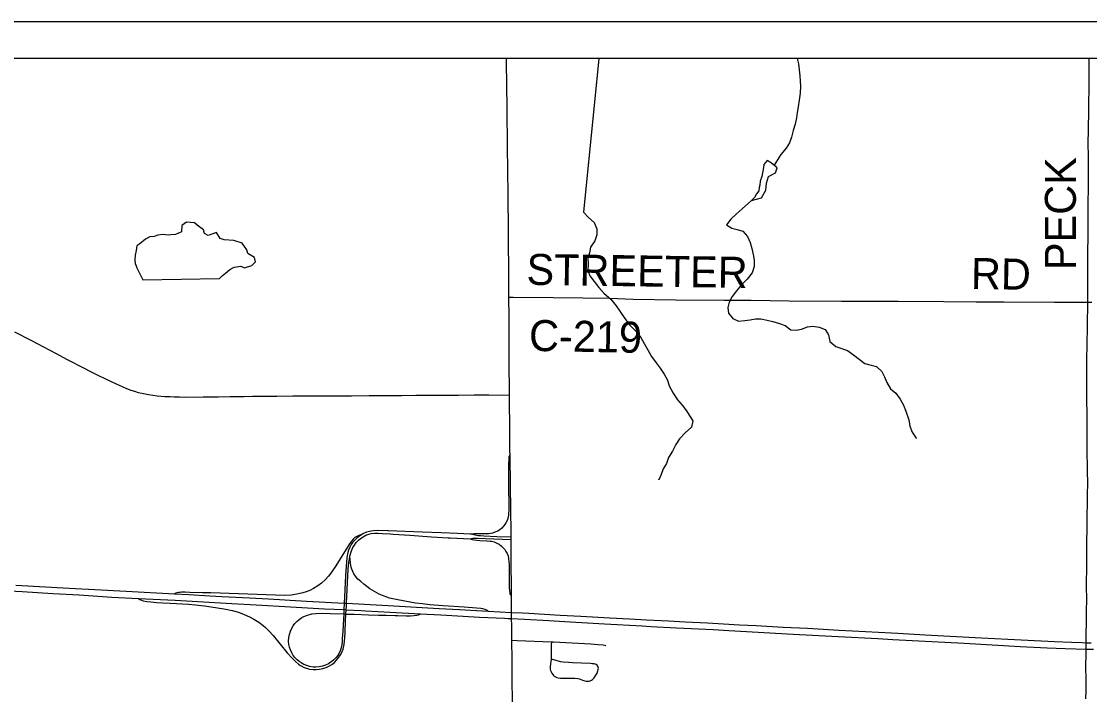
# Model space of a CAD drawing. Extents: x 0 to 34, y 0 to 22.
# Drawn here: x 24.966 to 26.924, y 15.541 to 16.775 of the extents above; entities that cross this region are included whole.
import ezdxf

# ---------------------------------------------------------------- set-up
doc = ezdxf.new("R2010")
doc.units = 0
for name, color, linetype in [('GM_X_Corporation', 7, 'Continuous'), ('GM_X_County_Road', 7, 'Continuous'), ('GM_X_County_Road_Text', 7, 'Continuous'), ('GM_X_Interchange_Ramps', 7, 'Continuous'), ('GM_X_Interstate_Route', 7, 'Continuous'), ('GM_X_Minor_Lake', 7, 'Continuous'), ('GM_X_Minor_River', 7, 'Continuous'), ('GM_X_State_Route', 7, 'Continuous'), ('GM_X_Township_Road', 7, 'Continuous'), ('SH_Data', 7, 'Continuous')]:
    doc.layers.add(name, color=color, linetype=linetype)

msp = doc.modelspace()

# ---------------------------------------------------------------- linework, layer by layer
at = {"layer": 'GM_X_Corporation'}
msp.add_lwpolyline([(27.8821, 16.7067), (23.0715, 16.7067), (23.0715, 12.7151)], dxfattribs=at)
at = {"layer": 'GM_X_County_Road'}
for points in [[(26.9208, 16.2606), (26.9208, 16.267), (26.9209, 16.3006), (26.9213, 16.3441), (26.9219, 16.3889), (26.9215, 16.4106), (26.9218, 16.4423), (26.9221, 16.469), (26.9223, 16.4951), (26.9225, 16.5131), (26.9221, 16.5316), (26.9219, 16.5477), (26.9222, 16.58), (26.9227, 16.6086), (26.9229, 16.6259), (26.9232, 16.6358), (26.9233, 16.6408), (26.9236, 16.6578), (26.9235, 16.6929), (26.9235, 16.7027), (26.9236, 16.7067)], [(25.86, 16.2697), (25.8681, 16.2697), (25.9413, 16.2689), (25.9953, 16.2685), (26.0445, 16.2678), (26.0877, 16.2661), (26.1655, 16.2648), (26.2546, 16.264), (26.3042, 16.264), (26.3734, 16.2631), (26.4694, 16.2624), (26.5166, 16.2622), (26.5732, 16.2622), (26.6571, 16.2616), (26.7167, 16.2613), (26.7676, 16.2608), (26.8602, 16.2604), (26.9208, 16.2606)], [(26.9177, 15.5337), (26.9178, 15.5492), (26.9179, 15.5673), (26.9178, 15.5753), (26.9177, 15.5865), (26.9177, 15.5908), (26.9179, 15.6182), (26.918, 15.6249), (26.918, 15.6319), (26.918, 15.6366), (26.9182, 15.6536), (26.9185, 15.6723), (26.9185, 15.6884), (26.9187, 15.6959), (26.919, 15.7145), (26.9189, 15.7412), (26.9193, 15.7778), (26.9192, 15.7915), (26.9192, 15.7988), (26.9192, 15.8007), (26.9192, 15.8048), (26.919, 15.8135), (26.9192, 15.8278), (26.9196, 15.8383), (26.9198, 15.8476), (26.92, 15.855), (26.92, 15.8579), (26.9201, 15.8721), (26.9203, 15.8889), (26.9207, 15.9088), (26.9208, 15.928), (26.9204, 15.9522), (26.92, 15.9925), (26.9201, 16.0145), (26.92, 16.0413), (26.9193, 16.0955), (26.9191, 16.1361), (26.9194, 16.1551), (26.9198, 16.1825), (26.9203, 16.2167), (26.9208, 16.2606)], [(26.9208, 16.2606), (26.9287, 16.2605)]]:
    msp.add_lwpolyline(points, dxfattribs=at)
at = {"layer": 'GM_X_Interchange_Ramps'}
msp.add_line((25.7526, 15.8286), (25.7889, 15.827), dxfattribs=at)
for points in [[(25.8621, 15.9806), (25.8615, 15.9803), (25.8609, 15.9798), (25.8603, 15.9784), (25.8601, 15.9772), (25.8597, 15.9722), (25.8593, 15.9644), (25.859, 15.9396), (25.8593, 15.9207), (25.8596, 15.8892), (25.8596, 15.8794), (25.8595, 15.8732), (25.8593, 15.8704), (25.8587, 15.8669), (25.858, 15.8642), (25.8567, 15.8604), (25.8545, 15.8559), (25.8527, 15.8529), (25.8504, 15.8498), (25.8473, 15.8466), (25.844, 15.844), (25.8397, 15.8412), (25.8345, 15.8388), (25.8297, 15.8372), (25.8261, 15.8366), (25.8226, 15.8363), (25.8162, 15.8363), (25.8104, 15.8363), (25.8023, 15.836), (25.7962, 15.836), (25.7892, 15.8357)], [(25.6382, 15.8416), (25.6187, 15.842), (25.612, 15.8416), (25.6047, 15.8404), (25.5988, 15.8389), (25.5933, 15.8365), (25.5918, 15.8356)], [(25.7892, 15.8357), (25.7658, 15.8365), (25.736, 15.8376), (25.701, 15.8389), (25.6392, 15.8416), (25.6382, 15.8416)], [(25.5918, 15.8356), (25.5886, 15.8344), (25.5847, 15.833), (25.581, 15.8313), (25.5778, 15.829), (25.5747, 15.8262), (25.572, 15.8231), (25.5681, 15.8175), (25.5508, 15.7902), (25.5428, 15.7776), (25.5334, 15.7637), (25.5293, 15.7583), (25.5235, 15.7518), (25.5166, 15.7456), (25.5096, 15.7405), (25.5021, 15.736), (25.4949, 15.7324), (25.4868, 15.7293), (25.4797, 15.7271), (25.4712, 15.7252), (25.4607, 15.7238), (25.4489, 15.7233), (25.4321, 15.7234), (25.314, 15.7277), (25.2982, 15.7281), (25.2753, 15.7287), (25.2666, 15.7289), (25.2602, 15.7289), (25.2568, 15.7288), (25.2546, 15.7284), (25.2516, 15.7278), (25.2495, 15.7271), (25.247, 15.7262)], [(25.5918, 15.8356), (25.587, 15.8325), (25.5819, 15.8286), (25.5776, 15.8246), (25.5742, 15.8205), (25.5712, 15.8164), (25.5685, 15.8113), (25.5661, 15.806), (25.5642, 15.7996), (25.563, 15.7923), (25.5622, 15.7839), (25.5618, 15.7768), (25.5608, 15.7592), (25.5588, 15.7209), (25.5582, 15.7089), (25.5577, 15.6971), (25.5573, 15.6892), (25.5568, 15.6793), (25.5556, 15.6574), (25.5547, 15.644), (25.5543, 15.6383), (25.5538, 15.6329), (25.5531, 15.6294), (25.552, 15.6255), (25.5507, 15.6214), (25.5487, 15.6173), (25.5457, 15.6128), (25.5429, 15.609), (25.5383, 15.6043), (25.5339, 15.6009), (25.5292, 15.5979), (25.5241, 15.5954), (25.5185, 15.5936), (25.5125, 15.5922), (25.5063, 15.5917), (25.5011, 15.592), (25.4947, 15.593), (25.4894, 15.5945), (25.4841, 15.5967), (25.4794, 15.5994), (25.4755, 15.6019), (25.4717, 15.6051), (25.4678, 15.6092), (25.4646, 15.6132), (25.4619, 15.6177), (25.4595, 15.6232), (25.458, 15.6283), (25.4568, 15.6331), (25.4563, 15.6393), (25.4569, 15.646), (25.4578, 15.6515), (25.4595, 15.6575), (25.4615, 15.662), (25.4645, 15.6674), (25.4679, 15.672), (25.4712, 15.6756), (25.4755, 15.6793), (25.4806, 15.6827), (25.4839, 15.6844), (25.4908, 15.6872), (25.4987, 15.6892), (25.5067, 15.6902), (25.516, 15.6905), (25.5327, 15.69), (25.5568, 15.6892)], [(25.5686, 15.7953), (25.5716, 15.8051), (25.574, 15.8107), (25.5768, 15.8155), (25.58, 15.8199), (25.5841, 15.8244), (25.5879, 15.8275), (25.593, 15.8308), (25.5979, 15.8333), (25.6035, 15.8353), (25.6077, 15.8364), (25.6137, 15.8373), (25.6204, 15.8374), (25.6285, 15.8367), (25.6423, 15.8358)], [(25.6423, 15.8358), (25.6482, 15.8354), (25.6784, 15.8335), (25.718, 15.8307), (25.7486, 15.8288), (25.7526, 15.8286)], [(25.7889, 15.827), (25.7912, 15.8277), (25.7939, 15.828), (25.7979, 15.8281), (25.8027, 15.828), (25.8326, 15.8268), (25.864, 15.8255)], [(25.7889, 15.827), (25.7926, 15.8258), (25.7965, 15.8249), (25.801, 15.8244), (25.8066, 15.8241), (25.8197, 15.8232), (25.8254, 15.8228), (25.8281, 15.8225), (25.8306, 15.822), (25.8328, 15.8214), (25.8353, 15.8204), (25.8381, 15.8192), (25.8424, 15.8168), (25.8463, 15.8137), (25.8491, 15.8109), (25.8523, 15.8071), (25.8546, 15.8038), (25.8568, 15.7998), (25.8584, 15.7956), (25.8595, 15.7902), (25.8601, 15.7852), (25.8603, 15.7793), (25.8604, 15.7591), (25.8604, 15.7516), (25.8607, 15.7369), (25.8615, 15.7279), (25.8619, 15.7261), (25.8628, 15.7243), (25.8636, 15.7235), (25.8647, 15.7228)], [(25.864, 15.8299), (25.8382, 15.8306), (25.814, 15.8318), (25.8079, 15.8322), (25.8038, 15.8326), (25.798, 15.8335), (25.793, 15.8345), (25.7892, 15.8357)], [(25.1814, 15.7176), (25.1835, 15.7159), (25.1865, 15.7144), (25.1898, 15.7134), (25.1965, 15.7123), (25.2036, 15.7113), (25.2147, 15.7105), (25.2259, 15.7098), (25.2389, 15.7092), (25.2507, 15.7085), (25.2619, 15.7079), (25.273, 15.7069), (25.2854, 15.706), (25.3021, 15.7042), (25.3224, 15.7013), (25.3414, 15.698), (25.353, 15.6955), (25.3643, 15.6924), (25.3748, 15.6885), (25.3845, 15.6841), (25.3926, 15.6796), (25.4016, 15.674), (25.4095, 15.668), (25.4137, 15.6643), (25.4204, 15.6579), (25.428, 15.6496), (25.4539, 15.6178), (25.4626, 15.608), (25.4688, 15.6019), (25.4746, 15.5972), (25.4782, 15.5947), (25.4848, 15.5913), (25.4906, 15.5892), (25.4948, 15.5882), (25.501, 15.5874), (25.5066, 15.5874), (25.5128, 15.588), (25.5189, 15.5893), (25.5248, 15.5913), (25.5299, 15.5936), (25.5352, 15.5968), (25.5401, 15.6006), (25.5446, 15.6049), (25.5485, 15.6098), (25.5518, 15.615), (25.5545, 15.6206), (25.556, 15.6247), (25.5579, 15.6332), (25.5592, 15.6455), (25.5598, 15.6561), (25.5608, 15.6772), (25.5614, 15.6891), (25.5618, 15.6968), (25.5621, 15.7033), (25.5624, 15.7087), (25.5636, 15.7338), (25.5657, 15.771), (25.5669, 15.784), (25.5676, 15.7895), (25.5686, 15.7953)], [(25.8223, 15.6945), (25.8202, 15.6955), (25.8168, 15.6972), (25.8124, 15.6985), (25.8084, 15.6992), (25.8008, 15.6999), (25.7779, 15.7015), (25.7395, 15.7039), (25.7154, 15.7059), (25.7018, 15.7075), (25.6889, 15.7093), (25.6693, 15.7125), (25.6534, 15.7155), (25.6413, 15.7184), (25.6313, 15.7217), (25.6222, 15.7256), (25.6134, 15.7302), (25.605, 15.7355), (25.594, 15.7437), (25.5884, 15.7486), (25.5834, 15.7532), (25.5789, 15.7584), (25.5759, 15.763), (25.5737, 15.7669), (25.572, 15.7715), (25.571, 15.7752), (25.5698, 15.782), (25.5686, 15.7953)], [(25.5579, 15.6892), (25.5614, 15.6891), (25.5678, 15.6889), (25.5764, 15.6886), (25.6025, 15.6876), (25.6213, 15.6871), (25.6348, 15.6868), (25.6514, 15.6862), (25.6558, 15.6861), (25.6716, 15.6857), (25.6796, 15.6857), (25.6856, 15.6861), (25.6911, 15.6868), (25.6942, 15.6879), (25.6982, 15.6896)]]:
    msp.add_lwpolyline(points, dxfattribs=at)
at = {"layer": 'GM_X_Interstate_Route'}
for points in [[(24.9207, 15.7329), (24.9681, 15.7301), (25.0241, 15.7269), (25.0725, 15.7241), (25.1322, 15.7202), (25.1814, 15.7176), (25.2483, 15.7143), (25.3104, 15.7108), (25.3523, 15.7084), (25.3966, 15.7059), (25.4596, 15.7025), (25.5222, 15.6989), (25.5577, 15.6971), (25.5618, 15.6968), (25.5895, 15.6954)], [(24.9563, 15.7419), (25.0543, 15.7365), (25.1008, 15.7339), (25.1586, 15.7308), (25.247, 15.7262)], [(25.247, 15.7262), (25.2731, 15.7247), (25.3119, 15.7225), (25.3339, 15.7213), (25.3845, 15.7185), (25.4194, 15.7167), (25.4888, 15.7128), (25.5465, 15.7095), (25.5582, 15.7089), (25.5624, 15.7087), (25.639, 15.7046), (25.7325, 15.6995), (25.7697, 15.6974), (25.8223, 15.6945), (25.8649, 15.6921), (25.8847, 15.691), (25.8963, 15.6904), (25.9542, 15.6873), (25.9916, 15.6854), (26.045, 15.6824), (26.081, 15.6804), (26.1123, 15.6787), (26.1525, 15.6765), (26.1828, 15.6748), (26.2238, 15.6728), (26.2824, 15.6696), (26.3132, 15.6678), (26.3624, 15.6653), (26.4074, 15.6629), (26.4369, 15.6613), (26.4649, 15.6597), (26.4895, 15.6582), (26.5374, 15.6557), (26.5726, 15.6539), (26.6231, 15.651), (26.7261, 15.6454), (26.7988, 15.6416), (26.8601, 15.6386), (26.8909, 15.6373), (26.9106, 15.6368), (26.918, 15.6366), (26.927, 15.6365)], [(25.5895, 15.6954), (25.5974, 15.695), (25.6422, 15.6926), (25.6982, 15.6896), (25.735, 15.6875), (25.776, 15.6852), (25.8061, 15.6836), (25.8517, 15.6813), (25.8578, 15.681)], [(25.8578, 15.681), (25.865, 15.6807), (25.8885, 15.6796), (25.9333, 15.6771), (25.9723, 15.6749), (26.0039, 15.6732), (26.0354, 15.6714), (26.1041, 15.6675), (26.1204, 15.6665), (26.1669, 15.6641), (26.2344, 15.6605), (26.263, 15.6589), (26.381, 15.6523), (26.4637, 15.648), (26.5363, 15.644), (26.564, 15.6425), (26.6943, 15.6355), (26.797, 15.6299), (26.8468, 15.6272), (26.8797, 15.6258), (26.918, 15.6249), (26.9314, 15.6246)]]:
    msp.add_lwpolyline(points, dxfattribs=at)
at = {"layer": 'GM_X_Minor_Lake'}
for p, q in [((26.3264, 16.5073), (26.3234, 16.4906)), ((25.178, 16.3232), (25.1891, 16.3016))]:
    msp.add_line(p, q, dxfattribs=at)
for points in [[(26.3234, 16.4906), (26.3204, 16.4822), (26.3197, 16.4746), (26.319, 16.4708), (26.3178, 16.4643), (26.3141, 16.459), (26.3103, 16.4521), (26.3048, 16.447), (26.3228, 16.4514), (26.3307, 16.4655), (26.3322, 16.4785), (26.3356, 16.4906), (26.3488, 16.4975), (26.3518, 16.5067), (26.3411, 16.515), (26.3332, 16.5199), (26.3271, 16.5126), (26.3264, 16.5073)], [(25.1891, 16.3016), (25.3295, 16.3039), (25.3344, 16.3084), (25.3408, 16.3138), (25.3484, 16.3203), (25.3564, 16.3245), (25.3685, 16.3261), (25.3753, 16.3235), (25.3886, 16.3277), (25.3954, 16.3342), (25.3939, 16.3422), (25.3817, 16.3493), (25.3794, 16.3562), (25.3713, 16.3687), (25.3558, 16.3732), (25.3383, 16.3746), (25.3307, 16.3772), (25.3238, 16.3878), (25.309, 16.3828), (25.3022, 16.3862), (25.3003, 16.393), (25.2888, 16.4017), (25.2839, 16.4055), (25.2694, 16.4073), (25.2604, 16.4008), (25.2597, 16.389), (25.2491, 16.3844), (25.2403, 16.384), (25.2354, 16.3832), (25.2259, 16.3847), (25.2168, 16.3831), (25.2096, 16.3808), (25.202, 16.38), (25.1941, 16.3758), (25.1835, 16.3674), (25.1782, 16.3639), (25.1767, 16.3548), (25.1748, 16.3464), (25.1745, 16.3377), (25.1749, 16.3312), (25.1768, 16.327), (25.178, 16.3232)]]:
    msp.add_lwpolyline(points, dxfattribs=at)
at = {"layer": 'GM_X_Minor_River'}
for points in [[(26.0249, 16.7067), (25.9969, 16.4254), (26.0057, 16.4156), (26.016, 16.4062), (26.0214, 16.3948), (26.021, 16.3838), (26.0173, 16.3731), (26.0094, 16.3609), (26.0075, 16.3506), (26.0049, 16.3407), (26.005, 16.3308), (26.0046, 16.3187), (26.0081, 16.3084), (26.0161, 16.2986), (26.0249, 16.2872), (26.0344, 16.2766), (26.0466, 16.266), (26.0569, 16.2539), (26.0722, 16.2304), (26.0814, 16.218), (26.094, 16.2058), (26.1016, 16.196), (26.1077, 16.1846), (26.115, 16.1721), (26.1215, 16.1608), (26.1299, 16.1494), (26.1375, 16.1396), (26.1444, 16.1286), (26.1505, 16.1176), (26.154, 16.1073), (26.1613, 16.0937), (26.1693, 16.0816), (26.1773, 16.0717), (26.1857, 16.0611), (26.1907, 16.0535)], [(26.3885, 16.7067), (26.3908, 16.6973), (26.392, 16.6863), (26.3935, 16.6753), (26.3936, 16.6654), (26.3944, 16.6559), (26.3937, 16.6434), (26.3922, 16.6304), (26.3904, 16.6186), (26.3885, 16.608), (26.3871, 16.5981), (26.3845, 16.5867), (26.3811, 16.5749), (26.3777, 16.5627), (26.3744, 16.5524), (26.368, 16.5425), (26.3585, 16.531), (26.346, 16.5112)], [(26.3048, 16.447), (26.2873, 16.4315), (26.2763, 16.4215), (26.2665, 16.4124), (26.2589, 16.4021), (26.2688, 16.396), (26.2783, 16.3934), (26.2886, 16.3904), (26.2974, 16.3806), (26.3023, 16.3696), (26.3054, 16.3586), (26.3077, 16.3476), (26.3097, 16.3373), (26.3097, 16.3255), (26.3056, 16.3141), (26.2969, 16.3027), (26.2864, 16.292), (26.2769, 16.2813), (26.2694, 16.271), (26.2637, 16.2603), (26.2615, 16.2508), (26.2623, 16.2405), (26.2707, 16.2303), (26.281, 16.2258), (26.2927, 16.2266), (26.3022, 16.2282), (26.3117, 16.2301), (26.3216, 16.2298), (26.3333, 16.2276), (26.344, 16.225), (26.3561, 16.2216), (26.3664, 16.2175), (26.3767, 16.2099), (26.3866, 16.2089), (26.3964, 16.2112), (26.4074, 16.2154), (26.4169, 16.2166), (26.4287, 16.2148), (26.4397, 16.2106), (26.4458, 16.2004), (26.4485, 16.1883), (26.4592, 16.1792), (26.4809, 16.1721), (26.4919, 16.1642), (26.5022, 16.1562), (26.5125, 16.1479), (26.5239, 16.1453), (26.5337, 16.1427), (26.5433, 16.1336), (26.5483, 16.1234), (26.5525, 16.1131), (26.5594, 16.1018), (26.5693, 16.0935), (26.5773, 16.0825), (26.5834, 16.0719), (26.5873, 16.0605)], [(26.5873, 16.0605), (26.5928, 16.0451), (26.5949, 16.033), (26.5992, 16.022), (26.6065, 16.0115), (26.6068, 16.0115)], [(26.1907, 16.0535), (26.1971, 16.0432), (26.1945, 16.0317), (26.1833, 16.021), (26.1724, 16.0102), (26.1661, 15.9999), (26.1598, 15.9877), (26.1527, 15.9758), (26.1487, 15.9651), (26.1427, 15.9552), (26.1391, 15.9449), (26.1346, 15.935), (26.135, 15.9357)]]:
    msp.add_lwpolyline(points, dxfattribs=at)
at = {"layer": 'GM_X_State_Route'}
for points in [[(25.862, 15.9876), (25.8616, 16.02), (25.8611, 16.0902), (25.8607, 16.154), (25.8603, 16.2323), (25.86, 16.2697), (25.8597, 16.3), (25.8592, 16.3902), (25.8584, 16.4579), (25.8575, 16.5459), (25.8568, 16.6142), (25.8561, 16.6601), (25.8556, 16.6982), (25.8555, 16.7067)], [(25.8651, 15.6676), (25.865, 15.6807), (25.8649, 15.6921), (25.8647, 15.7228), (25.8646, 15.7281), (25.8642, 15.7922), (25.864, 15.8255), (25.864, 15.8299), (25.8639, 15.8382), (25.8628, 15.9236), (25.8621, 15.9806), (25.862, 15.9876)], [(25.8695, 15.2785), (25.8679, 15.3715), (25.8673, 15.4342), (25.8668, 15.4932), (25.8658, 15.6044), (25.8653, 15.6413), (25.8651, 15.6676)]]:
    msp.add_lwpolyline(points, dxfattribs=at)
at = {"layer": 'GM_X_Township_Road'}
for points in [[(24.9537, 16.2059), (24.9835, 16.1907), (25.0301, 16.1663), (25.0491, 16.1563), (25.0827, 16.1389), (25.091, 16.1345), (25.1055, 16.1272), (25.1207, 16.1198), (25.1405, 16.1106), (25.1509, 16.1061), (25.1594, 16.1024), (25.1668, 16.0995), (25.1741, 16.0972), (25.1805, 16.0952), (25.187, 16.0935), (25.1934, 16.0922), (25.1994, 16.091), (25.2076, 16.0899), (25.2151, 16.0891), (25.2293, 16.0879), (25.2392, 16.0874), (25.2467, 16.0871), (25.256, 16.0868), (25.268, 16.0867), (25.2995, 16.087), (25.3269, 16.0873), (25.349, 16.0876), (25.3747, 16.0879), (25.3901, 16.0881), (25.4093, 16.0883), (25.4345, 16.0885), (25.4638, 16.0886), (25.5103, 16.0887), (25.5407, 16.0889), (25.5718, 16.089), (25.6037, 16.0893), (25.635, 16.0895), (25.663, 16.0897), (25.6894, 16.0899), (25.7089, 16.09), (25.736, 16.0901), (25.7675, 16.0903), (25.7964, 16.0904), (25.823, 16.0904), (25.8611, 16.0902)], [(25.8653, 15.6413), (25.8754, 15.6409), (25.9378, 15.6382), (25.9419, 15.638), (26.0102, 15.6344), (26.0238, 15.6335), (26.033, 15.6324), (26.0379, 15.6316)], [(25.9378, 15.6382), (25.9376, 15.6325), (25.9372, 15.6145), (25.9373, 15.6064), (25.9357, 15.593), (25.9359, 15.588), (25.9363, 15.5855), (25.9372, 15.5832), (25.9384, 15.581), (25.9418, 15.5766), (25.9432, 15.5754), (25.9453, 15.574), (25.9476, 15.5731), (25.9506, 15.5723), (25.9543, 15.5718), (25.9599, 15.5717), (25.9742, 15.5717), (25.981, 15.5714), (25.9866, 15.5709), (25.9896, 15.5702), (25.9948, 15.5681), (25.9989, 15.5666), (26.0019, 15.5659), (26.005, 15.5658), (26.0074, 15.5662), (26.0092, 15.5668), (26.0114, 15.568), (26.0134, 15.5694), (26.0157, 15.5715), (26.0176, 15.574), (26.0196, 15.5771), (26.0216, 15.581), (26.0232, 15.585), (26.0239, 15.5874), (26.024, 15.5893), (26.0231, 15.5933), (26.0227, 15.5938), (26.0216, 15.5953), (26.0201, 15.5964), (26.0184, 15.5972), (26.016, 15.5978), (26.0129, 15.5981), (26.0098, 15.5982), (25.9767, 15.5996), (25.9692, 15.6), (25.9597, 15.6009), (25.9546, 15.6016), (25.9464, 15.6038), (25.9373, 15.6064)]]:
    msp.add_lwpolyline(points, dxfattribs=at)
at = {"layer": 'SH_Data'}
msp.add_line((22.9992, 16.7749), (29.9992, 16.7749), dxfattribs=at)

# ---------------------------------------------------------------- texts
at = {"layer": 'GM_X_County_Road_Text'}
for s, rotation, p in [('PECK', 90, (26.8992, 16.3191)), ('STREETER', 359.1747, (25.892, 16.2923)), ('RD', 359.0186, (26.7065, 16.2848)), ('C-219', 358.9205, (25.8965, 16.1713))]:
    msp.add_text(s, height=0.05682, rotation=rotation, dxfattribs=at).set_placement(p)

doc.saveas('drawing.dxf')
